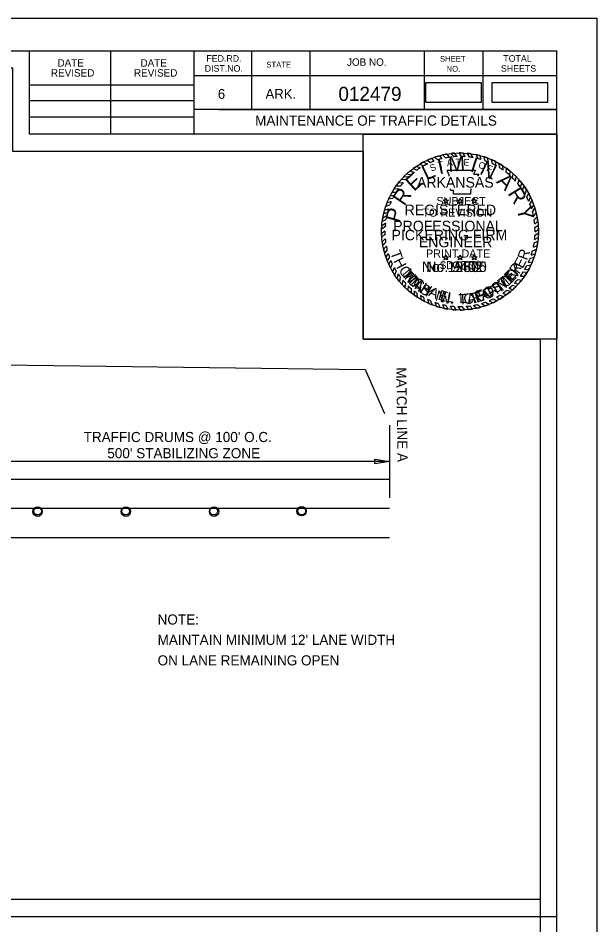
# Model space of a CAD drawing. Extents: x 1373222 to 1374279, y 380783 to 380996.
# Drawn here: x 1373848.3 to 1373917, y 380888.9 to 380996.5 of the extents above; entities that cross this region are included whole.
import ezdxf

# ---------------------------------------------------------------- set-up
doc = ezdxf.new("R2010")
doc.units = 0
for name, color, linetype in [('Default', 7, 'Continuous'), ('R_Border', 7, 'Continuous'), ('R_Border Notes', 7, 'Continuous'), ('R_Border Plan-Plan', 7, 'Continuous'), ('R_No Plot', 7, 'Continuous'), ('STAMP_PE_CRAFTON', 7, 'Continuous'), ('STAMP_PE_FOSTER', 7, 'Continuous'), ('STAMP_PE_SEAL-INFO', 7, 'Continuous'), ('STAMP_PE_TAEGTMEYER', 7, 'Continuous'), ('STAMP_PE_TXT', 7, 'Continuous'), ('STAMP_PRELIMINARY', 7, 'Continuous')]:
    doc.layers.add(name, color=color, linetype=linetype)

msp = doc.modelspace()

# ---------------------------------------------------------------- linework, layer by layer
at = {"layer": 'Default'}
for p, q in [((1373892.42, 380948.17), (1373892.42, 380939.56)), ((1373890.68, 380943.6), (1373890.68, 380944.12)), ((1373890.68, 380944.12), (1373892.42, 380943.86)), ((1373892.42, 380943.86), (1373840.26, 380943.86)), ((1373892.42, 380943.86), (1373890.68, 380943.6)), ((1373608.96, 380941.78), (1373892.42, 380941.78)), ((1373608.96, 380938.31), (1373892.42, 380938.31)), ((1373608.96, 380934.83), (1373892.42, 380934.83))]:
    msp.add_line(p, q, dxfattribs=at)
for points in [[(1373896.67, 380986.5), (1373903.35, 380986.5), (1373903.35, 380988.81), (1373896.67, 380988.81)], [(1373904.54, 380986.51), (1373911.22, 380986.51), (1373911.22, 380988.82), (1373904.54, 380988.82)]]:
    msp.add_lwpolyline(points, close=True, dxfattribs=at)
msp.add_lwpolyline([(1373750.83, 380950.03), (1373754.78, 380955.27), (1373838.44, 380955.36), (1373840.05, 380960.2), (1373840.19, 380955.43), (1373889.53, 380954.77), (1373891.81, 380949.57)], dxfattribs=at)
for centre, major_axis in [((1373850.61, 380937.91), (0, 0.563)), ((1373850.63, 380937.97), (0, 0.458)), ((1373861.1, 380937.91), (0, 0.563)), ((1373861.08, 380937.97), (0, 0.458)), ((1373871.58, 380937.91), (0, 0.563)), ((1373871.54, 380937.97), (0, 0.458)), ((1373881.96, 380937.96), (0, 0.563)), ((1373881.99, 380937.97), (0, 0.458))]:
    msp.add_ellipse(centre, major_axis=major_axis, ratio=0.99998, dxfattribs=at)
at = {"layer": 'R_Border'}
for p, q in [((1373596.1, 380992.59), (1373912.28, 380992.59)), ((1373849.64, 380982.71), (1373849.64, 380992.59)), ((1373859.32, 380982.71), (1373859.32, 380992.59)), ((1373869.18, 380992.59), (1373869.18, 380982.71)), ((1373876.02, 380992.59), (1373876.02, 380985.65)), ((1373882.96, 380992.59), (1373882.96, 380985.65)), ((1373896.54, 380992.59), (1373896.54, 380985.65)), ((1373903.48, 380992.59), (1373903.48, 380985.65)), ((1373912.28, 380787.13), (1373912.28, 380992.59)), ((1373912.28, 380989.65), (1373869.18, 380989.65)), ((1373912.28, 380989.67), (1373912.28, 380989.67)), ((1373849.64, 380988.57), (1373869.18, 380988.57)), ((1373849.64, 380986.71), (1373869.18, 380986.71)), ((1373912.28, 380985.65), (1373869.18, 380985.65)), ((1373872.14, 380985.65), (1373912.28, 380985.65)), ((1373849.64, 380984.77), (1373869.18, 380984.77)), ((1373912.28, 380982.71), (1373849.64, 380982.71))]:
    msp.add_line(p, q, dxfattribs=at)
at = {"layer": 'R_Border Plan-Plan'}
msp.add_line((1373596.1, 380889.86), (1373912.28, 380889.86), dxfattribs=at)
at = {"layer": 'R_No Plot'}
for points in [[(1373583.69, 380996.49), (1373917.03, 380996.49), (1373917.03, 380783.15), (1373583.69, 380783.15)], [(1373910.28, 380891.86), (1373598.1, 380891.86), (1373598.1, 380990.59), (1373847.64, 380990.59), (1373847.64, 380980.71), (1373865.18, 380980.71), (1373889.28, 380980.71), (1373889.28, 380958.38), (1373910.28, 380958.38)], [(1373598.1, 380990.59), (1373847.64, 380990.59), (1373847.64, 380980.71), (1373865.18, 380980.71), (1373889.28, 380980.71), (1373889.28, 380958.38), (1373910.28, 380958.38), (1373910.28, 380789.13), (1373598.1, 380789.13)], [(1373889.28, 380982.71), (1373912.28, 380982.71), (1373912.28, 380958.38), (1373889.28, 380958.38)]]:
    msp.add_lwpolyline(points, close=True, dxfattribs=at)
at = {"layer": 'STAMP_PE_SEAL-INFO'}
for p, q in [((1373896.88, 380979.62), (1373897.27, 380979.35)), ((1373897.39, 380979.84), (1373897.69, 380979.51)), ((1373897.74, 380979.97), (1373898.12, 380979.66)), ((1373898.33, 380980.15), (1373898.62, 380979.8)), ((1373898.72, 380980.25), (1373899.07, 380979.9)), ((1373899.2, 380980.34), (1373899.5, 380979.98)), ((1373899.72, 380980.42), (1373900, 380980.03)), ((1373900.45, 380980.06), (1373900.14, 380980.46)), ((1373900.95, 380980.07), (1373900.67, 380980.48)), ((1373901.41, 380980.05), (1373901.15, 380980.47)), ((1373901.91, 380980), (1373901.62, 380980.44)), ((1373902.34, 380979.93), (1373902.08, 380980.39)), ((1373902.9, 380979.81), (1373902.73, 380980.27)), ((1373903.3, 380979.7), (1373903.14, 380980.17)), ((1373903.75, 380979.56), (1373903.61, 380980.04)), ((1373904.17, 380979.4), (1373904.03, 380979.89)), ((1373904.63, 380979.19), (1373904.53, 380979.69)), ((1373905.08, 380978.96), (1373904.99, 380979.47)), ((1373895.2, 380978.65), (1373895.65, 380978.45)), ((1373895.62, 380978.92), (1373896.06, 380978.72)), ((1373896, 380979.16), (1373896.44, 380978.94)), ((1373896.45, 380979.41), (1373896.92, 380979.19)), ((1373899.25, 380978.45), (1373902.6, 380978.45)), ((1373899.37, 380978.14), (1373899.25, 380978.45)), ((1373902.6, 380978.45), (1373902.37, 380977.95)), ((1373905.47, 380978.74), (1373905.43, 380979.24)), ((1373905.9, 380978.45), (1373905.87, 380978.96)), ((1373906.26, 380978.18), (1373906.3, 380978.67)), ((1373893.82, 380977.36), (1373894.34, 380977.32)), ((1373894.14, 380977.7), (1373894.69, 380977.66)), ((1373894.48, 380978.02), (1373894.94, 380977.89)), ((1373894.82, 380978.32), (1373895.35, 380978.22)), ((1373899.48, 380977.84), (1373899.37, 380978.14)), ((1373899.48, 380977.73), (1373899.48, 380977.84)), ((1373902.37, 380977.95), (1373903, 380977.95)), ((1373903, 380977.95), (1373902.86, 380977.73)), ((1373906.71, 380977.81), (1373906.73, 380978.33)), ((1373907.02, 380977.52), (1373907.09, 380978.02)), ((1373907.38, 380977.14), (1373907.45, 380977.67)), ((1373892.96, 380976.23), (1373893.48, 380976.27)), ((1373893.19, 380976.58), (1373893.7, 380976.57)), ((1373893.47, 380976.95), (1373894.02, 380976.97)), ((1373899.68, 380976.02), (1373899.65, 380976.24)), ((1373902.11, 380976.24), (1373902.04, 380975.93)), ((1373907.65, 380976.83), (1373907.79, 380977.3)), ((1373907.98, 380976.41), (1373908.11, 380976.91)), ((1373908.2, 380976.1), (1373908.38, 380976.56)), ((1373892.48, 380975.41), (1373892.98, 380975.47)), ((1373892.71, 380975.83), (1373893.2, 380975.85)), ((1373899.99, 380976.02), (1373899.68, 380976.02)), ((1373899.99, 380975.59), (1373899.99, 380976.02)), ((1373902.02, 380975.59), (1373899.99, 380975.59)), ((1373902.04, 380975.93), (1373902.02, 380975.59)), ((1373908.51, 380975.6), (1373908.69, 380976.09)), ((1373908.71, 380975.23), (1373908.93, 380975.68)), ((1373908.94, 380974.75), (1373909.16, 380975.23)), ((1373891.96, 380974.18), (1373892.45, 380974.32)), ((1373892.11, 380974.59), (1373892.62, 380974.73)), ((1373892.29, 380975.02), (1373892.8, 380975.12)), ((1373909.08, 380974.41), (1373909.34, 380974.84)), ((1373909.27, 380973.86), (1373909.54, 380974.34)), ((1373892.06, 380973.02), (1373891.6, 380972.77)), ((1373891.7, 380973.27), (1373892.17, 380973.46)), ((1373891.8, 380973.68), (1373892.28, 380973.85)), ((1373909.38, 380973.5), (1373909.67, 380973.95)), ((1373909.51, 380972.94), (1373909.83, 380973.39)), ((1373891.92, 380972.13), (1373891.48, 380971.85)), ((1373891.98, 380972.56), (1373891.53, 380972.34)), ((1373909.58, 380972.56), (1373909.94, 380972.91)), ((1373909.65, 380972.05), (1373910.02, 380972.39)), ((1373909.68, 380971.63), (1373910.07, 380971.92)), ((1373891.88, 380971.7), (1373891.46, 380971.45)), ((1373891.87, 380971.21), (1373891.46, 380970.87)), ((1373909.68, 380970.71), (1373910.1, 380970.99)), ((1373909.69, 380971.11), (1373910.1, 380971.44)), ((1373891.87, 380970.8), (1373891.48, 380970.48)), ((1373891.91, 380970.31), (1373891.53, 380969.95)), ((1373891.96, 380969.88), (1373891.6, 380969.51)), ((1373909.59, 380969.81), (1373910.03, 380970.03)), ((1373909.64, 380970.2), (1373910.08, 380970.46)), ((1373892.04, 380969.42), (1373891.7, 380969.05)), ((1373892.13, 380969), (1373891.82, 380968.59)), ((1373909.39, 380968.86), (1373909.86, 380969.06)), ((1373909.5, 380969.31), (1373909.96, 380969.51)), ((1373892.25, 380968.55), (1373891.96, 380968.14)), ((1373892.39, 380968.13), (1373892.11, 380967.72)), ((1373892.56, 380967.7), (1373892.3, 380967.28)), ((1373909.11, 380967.99), (1373909.59, 380968.12)), ((1373909.25, 380968.37), (1373909.74, 380968.57)), ((1373892.73, 380967.32), (1373892.51, 380966.86)), ((1373892.97, 380966.86), (1373892.78, 380966.37)), ((1373908.46, 380966.64), (1373908.96, 380966.69)), ((1373908.74, 380967.14), (1373909.22, 380967.21)), ((1373908.9, 380967.47), (1373909.39, 380967.57)), ((1373893.2, 380966.46), (1373893.02, 380965.99)), ((1373893.41, 380966.15), (1373893.3, 380965.6)), ((1373893.69, 380965.76), (1373893.58, 380965.23)), ((1373907.64, 380965.47), (1373908.11, 380965.39)), ((1373907.95, 380965.86), (1373908.46, 380965.87)), ((1373908.29, 380966.36), (1373908.77, 380966.35)), ((1373893.99, 380965.38), (1373893.9, 380964.86)), ((1373894.29, 380965.04), (1373894.23, 380964.52)), ((1373894.62, 380964.72), (1373894.59, 380964.19)), ((1373894.96, 380964.4), (1373894.96, 380963.87)), ((1373906.6, 380964.4), (1373907.07, 380964.28)), ((1373907.01, 380964.78), (1373907.45, 380964.64)), ((1373907.26, 380965.04), (1373907.74, 380964.95)), ((1373895.32, 380964.11), (1373895.34, 380963.58)), ((1373895.66, 380963.86), (1373895.69, 380963.34)), ((1373896.09, 380963.58), (1373896.15, 380963.07)), ((1373896.44, 380963.37), (1373896.53, 380962.86)), ((1373905.11, 380963.36), (1373905.53, 380963.13)), ((1373905.53, 380963.61), (1373905.98, 380963.41)), ((1373905.87, 380963.84), (1373906.31, 380963.65)), ((1373906.33, 380964.18), (1373906.8, 380964.04)), ((1373896.92, 380963.12), (1373897.07, 380962.6)), ((1373897.29, 380962.95), (1373897.46, 380962.44)), ((1373897.78, 380962.76), (1373897.99, 380962.26)), ((1373898.19, 380962.63), (1373898.42, 380962.14)), ((1373898.7, 380962.49), (1373898.91, 380962.02)), ((1373899.1, 380962.4), (1373899.34, 380961.94)), ((1373899.6, 380962.32), (1373899.84, 380961.88)), ((1373900.03, 380962.27), (1373900.31, 380961.84)), ((1373900.52, 380962.25), (1373900.82, 380961.83)), ((1373900.98, 380962.24), (1373901.32, 380961.85)), ((1373901.5, 380962.27), (1373901.82, 380961.89)), ((1373901.93, 380962.32), (1373902.31, 380961.96)), ((1373902.38, 380962.39), (1373902.77, 380962.05)), ((1373902.87, 380962.49), (1373903.25, 380962.17)), ((1373903.33, 380962.61), (1373903.75, 380962.32)), ((1373903.82, 380962.78), (1373904.27, 380962.51)), ((1373904.24, 380962.94), (1373904.67, 380962.68)), ((1373904.7, 380963.15), (1373905.19, 380962.94))]:
    msp.add_line(p, q, dxfattribs=at)
for radius, start, end in [(9.32, 111.3124, 114.7026), (8.91, 110.3086, 113.1659), (9.32, 105.2339, 109.0352), (8.91, 104.0352, 107.3615), (9.32, 99.7525, 102.7765), (8.91, 98.258, 101.0329), (9.32, 93.9381, 96.5517), (8.91, 92.1102, 95.0367), (9.32, 87.7298, 90.6707), (8.91, 85.9628, 88.9097), (9.32, 81.9732, 84.8236), (8.91, 79.9264, 82.696), (9.32, 75.3125, 77.9426), (8.91, 73.5575, 76.2314), (9.32, 69.6061, 72.3058), (8.91, 67.6248, 70.504), (9.32, 63.1329, 66.2704), (9.32, 123.6199, 126.5906), (8.91, 121.9746, 125.11), (9.32, 117.6544, 120.8099), (8.91, 115.6869, 119.1583), (8.91, 61.1558, 64.3784), (9.32, 56.9003, 60.0942), (8.91, 54.9238, 58.2702), (9.32, 50.3492, 53.7159), (9.32, 135.4021, 138.3031), (8.91, 133.1331, 136.2562), (9.32, 129.7326, 132.5376), (8.91, 127.5297, 130.9683), (8.91, 48.3016, 52.0395), (8.91, 42.2212, 45.5512), (9.32, 44.3405, 47.3929), (9.32, 147.0072, 149.899), (9.32, 141.6056, 144.4486), (8.91, 145.0197, 148.2104), (8.91, 139.301, 142.5873), (8.91, 36.135, 39.5311), (9.32, 38.1247, 41.2316), (9.32, 31.9614, 35.4294), (9.32, 152.864, 155.5189), (8.91, 151.0315, 153.573), (8.91, 29.9032, 33.6645), (8.91, 23.7732, 27.2211), (9.32, 25.9391, 29.0125), (9.32, 158.4077, 161.0701), (8.91, 156.3402, 159.2319), (8.91, 17.6802, 21.4251), (9.32, 19.9538, 23.3141), (9.32, 164.3068, 166.894), (8.91, 167.9048, 170.9039), (8.91, 162.4331, 165.0013), (8.91, 11.5444, 15.2364), (9.32, 13.8421, 17.4447), (9.32, 170.0003, 172.6878), (8.91, 173.73, 176.4734), (8.91, 5.7599, 9.0606), (9.32, 7.5852, 10.8621), (9.32, 1.7215, 4.7268), (9.32, 175.7409, 178.2066), (9.32, 181.7251, 184.1626), (8.91, 179.6454, 182.2633), (8.91, 359.7329, 3.0639), (9.32, 355.7156, 358.9569), (9.32, 187.4204, 190.1927), (8.91, 185.4539, 188.234), (8.91, 348.0778, 351.3435), (8.91, 353.8632, 357.1274), (9.32, 349.8305, 353.0885), (9.32, 193.0369, 195.9973), (8.91, 191.2274, 193.9858), (8.91, 341.777, 345.0925), (9.32, 343.8925, 347.035), (9.32, 198.8967, 201.6281), (8.91, 196.9675, 199.8353), (8.91, 202.7761, 205.4791), (8.91, 335.6038, 339.1858), (9.32, 337.3837, 340.9933), (9.32, 204.5479, 207.4328), (8.91, 208.7883, 211.7934), (8.91, 329.5549, 333.2076), (9.32, 331.4037, 334.9332), (9.32, 210.8636, 213.6571), (9.32, 216.6115, 219.491), (8.91, 214.1838, 217.2747), (8.91, 316.6531, 320.3711), (8.91, 323.5851, 327.4407), (9.32, 325.4405, 328.9872), (9.32, 222.48, 225.3801), (8.91, 220.3909, 223.3056), (8.91, 226.2494, 229.2407), (8.91, 310.7744, 314.3161), (9.32, 312.4518, 315.6633), (9.32, 318.2846, 321.8043), (9.32, 228.3665, 231.348), (8.91, 232.229, 234.9336), (9.32, 234.295, 236.9452), (8.91, 238.2223, 240.8353), (8.91, 299.0768, 302.1724), (9.32, 300.621, 303.8703), (8.91, 304.823, 308.5143), (9.32, 306.3721, 310.208), (9.32, 240.1977, 242.8613), (8.91, 244.3204, 246.9486), (9.32, 246.576, 249.1558), (8.91, 250.3491, 253.1216), (9.32, 252.5967, 255.3252), (8.91, 256.505, 259.1192), (8.91, 262.3783, 265.2012), (8.91, 268.3215, 271.277), (8.91, 274.6157, 277.4486), (8.91, 280.3459, 283.5814), (8.91, 286.6423, 289.9783), (9.32, 288.5709, 291.9733), (8.91, 292.8745, 296.1185), (9.32, 294.6481, 298.2166), (9.32, 258.4433, 261.1398), (9.32, 264.1978, 267.1009), (9.32, 270.2548, 273.3361), (9.32, 276.4239, 279.4357), (9.32, 282.3199, 285.3702)]:
    msp.add_arc((1373900.78, 380971.16), radius, start, end, dxfattribs=at)
at = {"layer": 'STAMP_PE_TXT'}
for p, q in [((1373898.96, 380974.73), (1373898.76, 380974.87)), ((1373898.76, 380974.87), (1373899.01, 380974.87)), ((1373898.88, 380974.49), (1373898.96, 380974.73)), ((1373899.08, 380974.64), (1373898.88, 380974.49)), ((1373899.01, 380974.87), (1373899.08, 380975.1)), ((1373899.08, 380975.1), (1373899.16, 380974.87)), ((1373899.28, 380974.49), (1373899.08, 380974.64)), ((1373899.16, 380974.87), (1373899.4, 380974.87)), ((1373899.4, 380974.87), (1373899.2, 380974.73)), ((1373899.2, 380974.73), (1373899.28, 380974.49)), ((1373900.66, 380974.73), (1373900.46, 380974.87)), ((1373900.46, 380974.87), (1373900.7, 380974.87)), ((1373900.58, 380974.49), (1373900.66, 380974.73)), ((1373900.78, 380974.64), (1373900.58, 380974.49)), ((1373900.7, 380974.87), (1373900.78, 380975.1)), ((1373900.78, 380975.1), (1373900.86, 380974.87)), ((1373900.98, 380974.49), (1373900.78, 380974.64)), ((1373900.86, 380974.87), (1373901.1, 380974.87)), ((1373901.1, 380974.87), (1373900.9, 380974.73)), ((1373900.9, 380974.73), (1373900.98, 380974.49)), ((1373902.35, 380974.73), (1373902.16, 380974.87)), ((1373902.16, 380974.87), (1373902.4, 380974.87)), ((1373902.28, 380974.49), (1373902.35, 380974.73)), ((1373902.48, 380974.64), (1373902.28, 380974.49)), ((1373902.4, 380974.87), (1373902.48, 380975.1)), ((1373902.48, 380975.1), (1373902.55, 380974.87)), ((1373902.68, 380974.49), (1373902.48, 380974.64)), ((1373902.55, 380974.87), (1373902.8, 380974.87)), ((1373902.8, 380974.87), (1373902.6, 380974.73)), ((1373902.6, 380974.73), (1373902.68, 380974.49)), ((1373898.96, 380968.02), (1373898.76, 380968.16)), ((1373898.76, 380968.16), (1373899.01, 380968.16)), ((1373898.88, 380967.79), (1373898.96, 380968.02)), ((1373899.08, 380967.93), (1373898.88, 380967.79)), ((1373899.01, 380968.16), (1373899.08, 380968.4)), ((1373899.08, 380968.4), (1373899.16, 380968.16)), ((1373899.28, 380967.79), (1373899.08, 380967.93)), ((1373899.16, 380968.16), (1373899.4, 380968.16)), ((1373899.4, 380968.16), (1373899.2, 380968.02)), ((1373899.2, 380968.02), (1373899.28, 380967.79)), ((1373900.66, 380968.02), (1373900.46, 380968.16)), ((1373900.46, 380968.16), (1373900.7, 380968.16)), ((1373900.58, 380967.79), (1373900.66, 380968.02)), ((1373900.78, 380967.93), (1373900.58, 380967.79)), ((1373900.7, 380968.16), (1373900.78, 380968.4)), ((1373900.78, 380968.4), (1373900.86, 380968.16)), ((1373900.98, 380967.79), (1373900.78, 380967.93)), ((1373900.86, 380968.16), (1373901.1, 380968.16)), ((1373901.1, 380968.16), (1373900.9, 380968.02)), ((1373900.9, 380968.02), (1373900.98, 380967.79)), ((1373902.35, 380968.02), (1373902.16, 380968.16)), ((1373902.16, 380968.16), (1373902.4, 380968.16)), ((1373902.28, 380967.79), (1373902.35, 380968.02)), ((1373902.48, 380967.93), (1373902.28, 380967.79)), ((1373902.4, 380968.16), (1373902.48, 380968.4)), ((1373902.48, 380968.4), (1373902.55, 380968.16)), ((1373902.68, 380967.79), (1373902.48, 380967.93)), ((1373902.55, 380968.16), (1373902.8, 380968.16)), ((1373902.8, 380968.16), (1373902.6, 380968.02)), ((1373902.6, 380968.02), (1373902.68, 380967.79))]:
    msp.add_line(p, q, dxfattribs=at)
at = {"layer": 'STAMP_PRELIMINARY'}
msp.add_circle((1373900.78, 380971.16), 9.32, dxfattribs=at)

# ---------------------------------------------------------------- texts
at = {"layer": 'Default'}
msp.add_text('MATCH LINE A', height=1.2, rotation=270.8059, dxfattribs=at).set_placement((1373893.2, 380955.03))
for s, p in [("TRAFFIC DRUMS @ 100' O.C.", (1373856.09, 380946.17)), ("500' STABILIZING ZONE", (1373858.9, 380944.25)), ('NOTE:', (1373864.87, 380924.51)), ("MAINTAIN MINIMUM 12' LANE WIDTH", (1373864.87, 380922.09)), ('ON LANE REMAINING OPEN', (1373864.87, 380919.66))]:
    msp.add_text(s, height=1.2, dxfattribs=at).set_placement(p)
at = {"layer": 'R_Border'}
for s, height, p in [('DATE', 0.879, (1373852.98, 380990.73)), ('DATE', 0.879, (1373862.84, 380990.73)), ('FED.RD.', 0.782, (1373870.66, 380991.31)), ('STATE', 0.684, (1373877.78, 380990.63)), ('JOB NO.', 0.879, (1373887.36, 380990.83)), ('SHEET', 0.684, (1373898.4, 380991.31)), ('TOTAL', 0.782, (1373905.92, 380991.31)), ('REVISED', 0.879, (1373852.2, 380989.55)), ('REVISED', 0.879, (1373862.06, 380989.55)), ('DIST.NO.', 0.782, (1373870.46, 380990.13)), ('NO.', 0.684, (1373899.18, 380990.13)), ('SHEETS', 0.782, (1373905.64, 380990.13)), ('6', 1.17, (1373872.02, 380986.91)), ('ARK.', 1.172, (1373877.68, 380986.91))]:
    msp.add_text(s, height=height, dxfattribs=at).set_placement(p)
at = {"layer": 'R_Border Notes'}
for s, height, p in [('012479', 1.68, (1373886.34, 380986.66)), ('MAINTENANCE OF TRAFFIC DETAILS', 1.2, (1373876.45, 380983.73))]:
    msp.add_text(s, height=height, dxfattribs=at).set_placement(p)
at = {"layer": 'STAMP_PE_CRAFTON'}
msp.add_text('No. 12370', height=1.25, dxfattribs=at).set_placement((1373896.24, 380966.35))
for s, rotation, p in [('T', 310.7442, (1373893.75, 380966.05)), ('N', 49.2411, (1373907.06, 380965.18)), ('O', 317.6422, (1373894.41, 380965.24)), ('O', 41.8391, (1373906.21, 380964.4)), ('N', 324.4537, (1373895.26, 380964.46)), ('Y', 331.1686, (1373896.29, 380963.74)), ('F', 28.7821, (1373904.44, 380963.28)), ('T', 34.1136, (1373905.36, 380963.79)), ('N', 347.4752, (1373898.35, 380962.82)), ('C', 6.0117, (1373901.25, 380962.5)), ('R', 14.8189, (1373902.35, 380962.61)), ('A', 20.5125, (1373903.46, 380962.91)), ('.', 356.8926, (1373899.58, 380962.55))]:
    msp.add_text(s, height=1.25, rotation=rotation, dxfattribs=at).set_placement(p)
at = {"layer": 'STAMP_PE_FOSTER'}
msp.add_text('No. 9402', height=1.25, dxfattribs=at).set_placement((1373896.77, 380966.35))
for s, rotation, p in [('M', 308.339, (1373893.9, 380966.18)), ('E', 46.9613, (1373906.78, 380965.15)), ('R', 54.5031, (1373907.5, 380965.97)), ('I', 314.1842, (1373894.69, 380965.24)), ('C', 319.8733, (1373895.05, 380964.89)), ('T', 39.4194, (1373905.92, 380964.4)), ('H', 327.7235, (1373895.98, 380964.15)), ('A', 335.7276, (1373896.96, 380963.57)), ('O', 23.719, (1373903.86, 380963.24)), ('S', 31.7234, (1373904.97, 380963.77)), ('E', 343.5779, (1373898.09, 380963.1)), ('L', 350.8115, (1373899.15, 380962.82)), ('L', 1.2666, (1373900.69, 380962.66)), ('F', 15.8691, (1373902.81, 380962.91)), ('.', 6.8035, (1373901.74, 380962.72))]:
    msp.add_text(s, height=1.2, rotation=rotation, dxfattribs=at).set_placement(p)
at = {"layer": 'STAMP_PE_TAEGTMEYER'}
for s, rotation, p in [('T', 289.646, (1373892.47, 380968.67)), ('R', 69.57, (1373908.72, 380967.67)), ('H', 296.7339, (1373892.83, 380967.68)), ('E', 63.0984, (1373908.23, 380966.69)), ('O', 303.7708, (1373893.43, 380966.57)), ('Y', 53.9986, (1373907.56, 380965.75)), ('M', 314.2033, (1373894.08, 380965.62)), ('M', 39.3, (1373905.78, 380964.05)), ('E', 46.8094, (1373906.82, 380964.93)), ('A', 321.0594, (1373895.04, 380964.66)), ('S', 327.8239, (1373895.87, 380964.01)), ('G', 23.3052, (1373903.78, 380963.02)), ('T', 31.466, (1373904.88, 380963.51)), ('N', 344.2727, (1373897.77, 380963.01)), ('T', 3.0061, (1373900.64, 380962.48)), ('A', 8.9826, (1373901.69, 380962.53)), ('E', 17.6836, (1373902.73, 380962.69)), ('.', 350.6464, (1373898.98, 380962.67))]:
    msp.add_text(s, height=1.25, rotation=rotation, dxfattribs=at).set_placement(p)
msp.add_text('No. 19605', height=1.25, dxfattribs=at).set_placement((1373896.24, 380966.35))
at = {"layer": 'STAMP_PE_TXT'}
for s, rotation, p in [('T', 16.311, (1373898.3, 380978.63)), ('A', 9.0679, (1373899.26, 380978.88)), ('T', 1.8248, (1373900.25, 380979.01)), ('E', 355.2002, (1373901.16, 380979.02)), ('S', 23.5541, (1373897.38, 380978.26)), ('O', 342.2506, (1373902.89, 380978.75)), ('F', 335.0075, (1373903.85, 380978.41))]:
    msp.add_text(s, height=0.781, rotation=rotation, dxfattribs=at).set_placement(p)
for s, p in [('ARKANSAS', (1373895.67, 380976.37)), ('REGISTERED', (1373894.2, 380973.1)), ('PROFESSIONAL', (1373892.85, 380971.19)), ('ENGINEER', (1373895.89, 380969.29))]:
    msp.add_text(s, height=1.25, dxfattribs=at).set_placement(p)
at = {"layer": 'STAMP_PRELIMINARY'}
for s, rotation, p in [('I', 12.5248, (1373898.32, 380977.94)), ('M', 3.1074, (1373899.42, 380978.25)), ('I', 342.3164, (1373901.88, 380978.32)), ('N', 333.9382, (1373902.99, 380978.04)), ('L', 25.513, (1373896.79, 380977.18)), ('E', 42.3578, (1373895.31, 380975.85)), ('A', 315.6579, (1373905.02, 380977.02)), ('R', 56.2292, (1373894.15, 380974.12)), ('R', 301.3831, (1373906.39, 380975.7)), ('Y', 283.2593, (1373907.48, 380973.92)), ('P', 73.913, (1373893.6, 380972.1))]:
    msp.add_text(s, height=1.8, rotation=rotation, dxfattribs=at).set_placement(p)
for s, height, p in [('SUBJECT', 0.96, (1373897.98, 380974.3)), ('TO REVISION', 0.96, (1373896.31, 380972.92)), ('PICKERING FIRM', 1.25, (1373892.65, 380970.12)), ('PRINT DATE', 0.96, (1373896.74, 380968.07)), ('$DATE$', 0.96, (1373898.41, 380966.69))]:
    msp.add_text(s, height=height, dxfattribs=at).set_placement(p)

doc.saveas('drawing.dxf')
